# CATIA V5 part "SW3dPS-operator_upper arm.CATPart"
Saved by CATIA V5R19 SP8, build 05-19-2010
Part number: SW3dPS-operator_upper arm
Revision: ANY
Definition: SW3dPS-operator_upper arm
Source: Unknown
Bounding box of the stored display mesh (mm): x -60.96 to 60.96, y -304.8 to 60.96, z -60.96 to 60.96
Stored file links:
  G:\EU_thinkMotion\CFAO_2010\MMS_groupe1\MMS_groupe1\OK\rragonneau\rragonneau\SW3dPS-operator_upper arm.CATPart
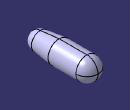
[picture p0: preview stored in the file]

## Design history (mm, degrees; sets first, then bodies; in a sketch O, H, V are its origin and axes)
Body1 "NONE" (main body)
  Solid1 "Manifold Solid #11114": solid without history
